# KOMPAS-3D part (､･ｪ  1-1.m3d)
File: created 29.01.2016 13:47:21, last saved 25.07.2016 11:41:04.
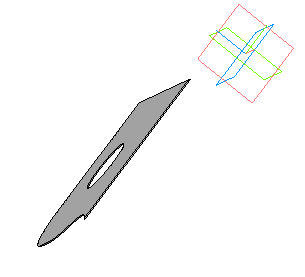
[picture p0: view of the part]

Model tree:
1. Эскиз:1
2. Операция выдавливания:1
     Толщина стенки 2 = 18; Расстояние 1 = 0.8
3. Эскиз:5
4. Вырезать элемент выдавливания:2
     Расстояние 1 = 10
5. Эскиз:6
6. Вырезать элемент выдавливания:3
     Расстояние 1 = 400
7. Эскиз:7
8. Вырезать элемент выдавливания:4
     Расстояние 1 = 400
